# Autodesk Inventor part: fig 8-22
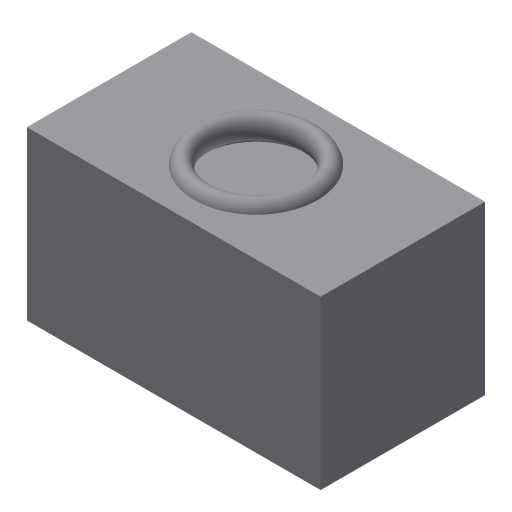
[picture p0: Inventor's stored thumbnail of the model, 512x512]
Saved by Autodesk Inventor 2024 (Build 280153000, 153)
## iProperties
Created: 2011-07
Part Number: fig 8-22
Material: Generic
Document SubType Name: Modeling
Designer: CadCim
Density: 1 g/cm^3
Appearance: Default
Author: CadCim
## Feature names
1. Extrusion1
2. Extrusion2
3. Sweep1
## Parameters: d0 = 14.25 mm, d1 = 0, d2 = 1.5 mm, d3 = 0, d4 = -4.25 mm, d5 = 0, d6 = 0
